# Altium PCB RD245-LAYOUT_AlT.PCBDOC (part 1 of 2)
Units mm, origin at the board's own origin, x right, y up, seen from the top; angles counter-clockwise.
Board outline 75 x 91 mm, 4 copper layers (TOP, Mid-Layer 1, Mid-Layer 2, BOTTOM), stack 0.711 mm thick; 95 components, 67 nets, 327 pads, 801 vias.
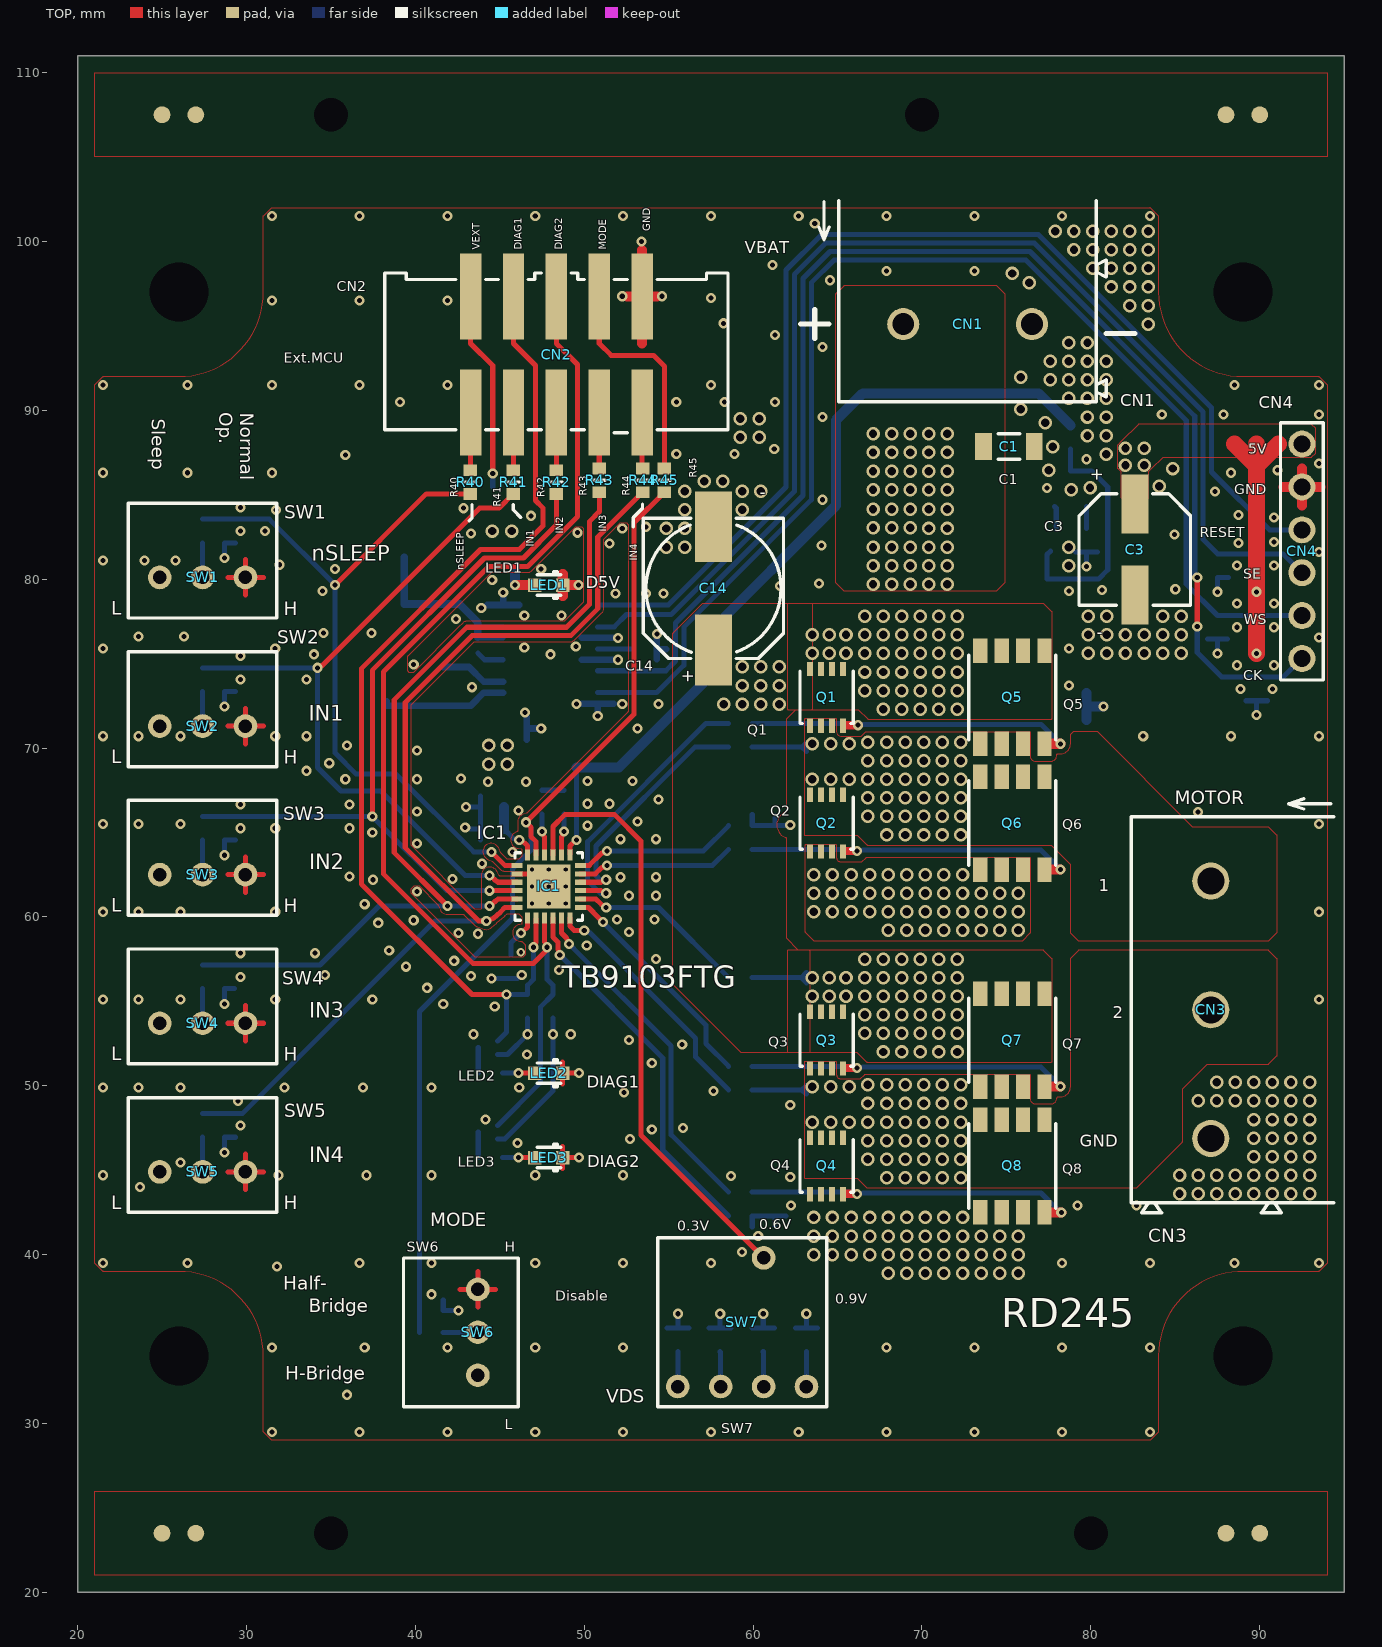
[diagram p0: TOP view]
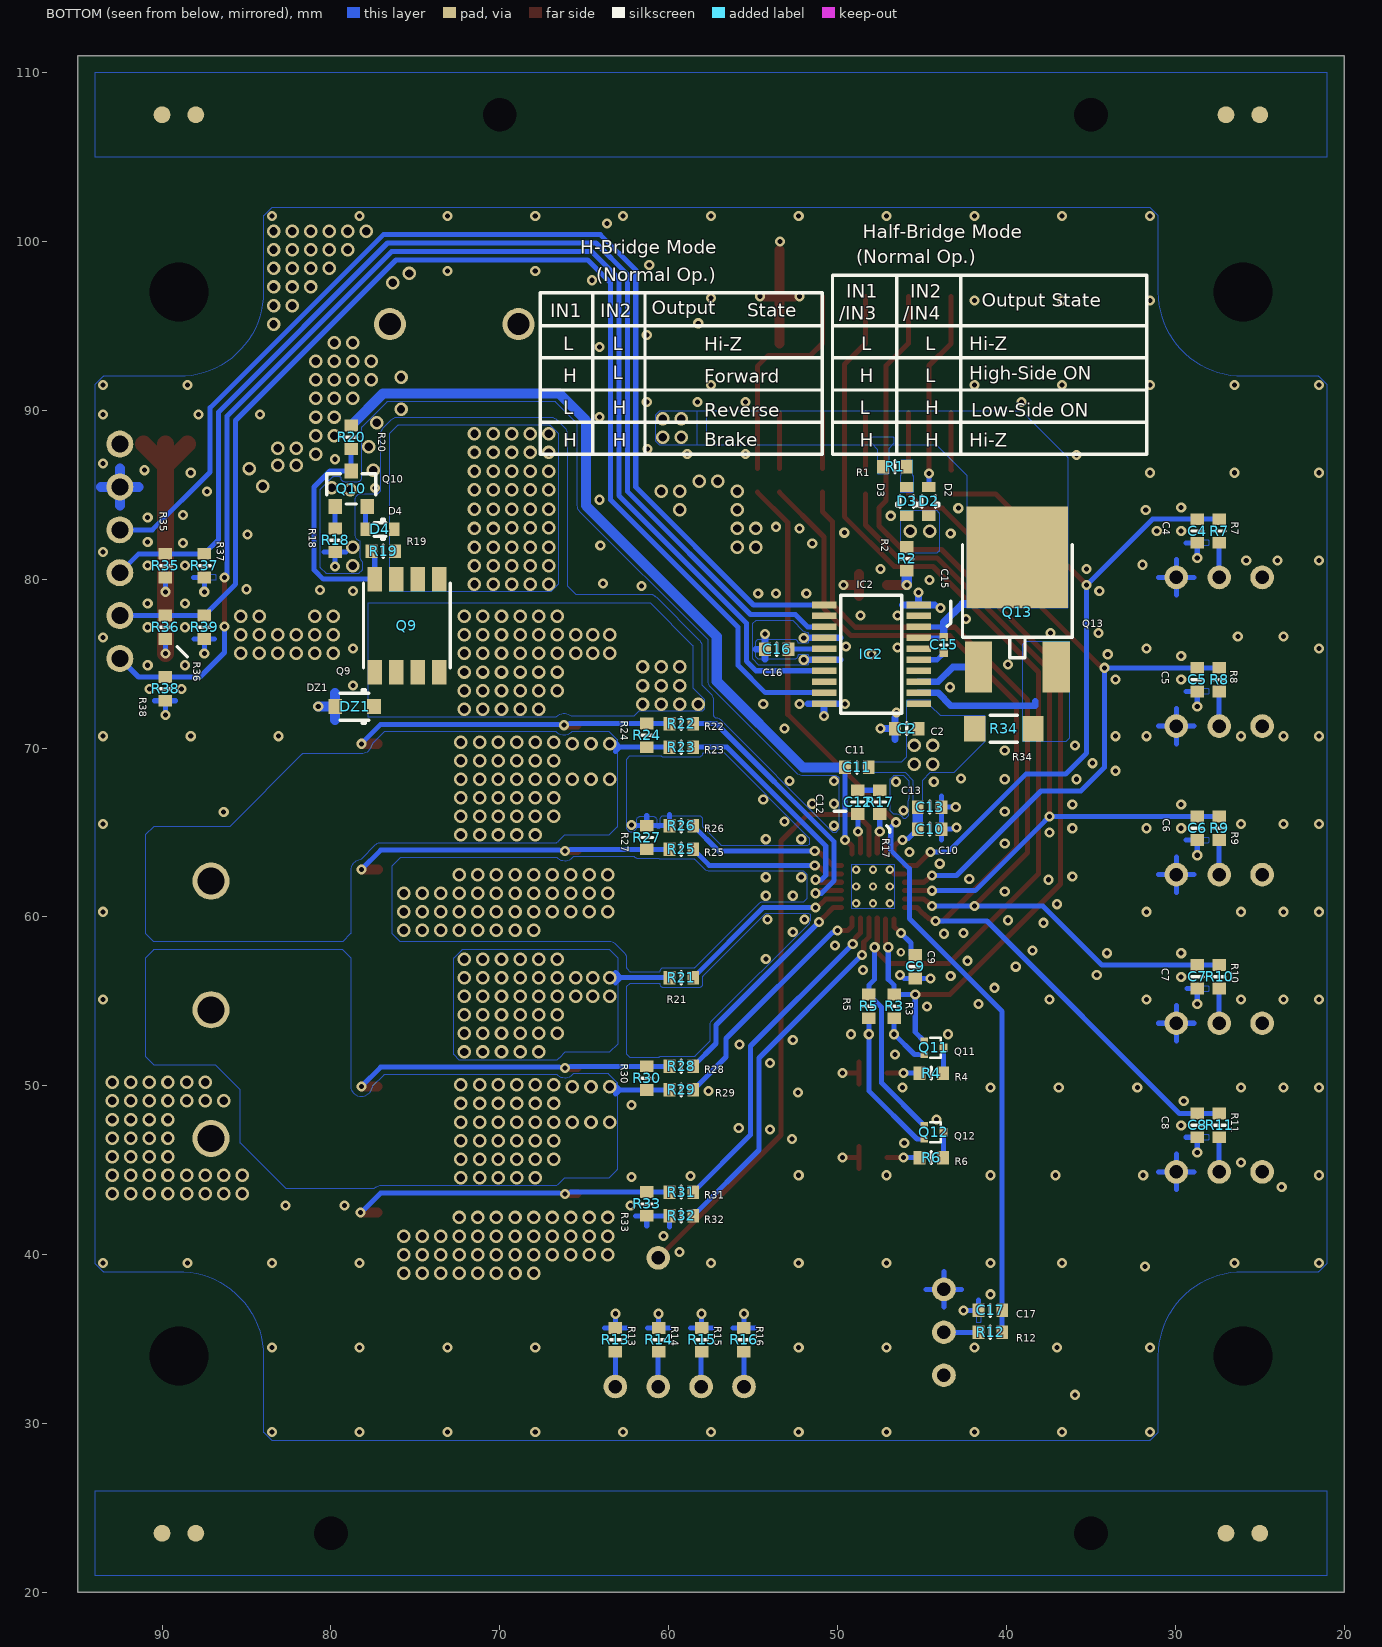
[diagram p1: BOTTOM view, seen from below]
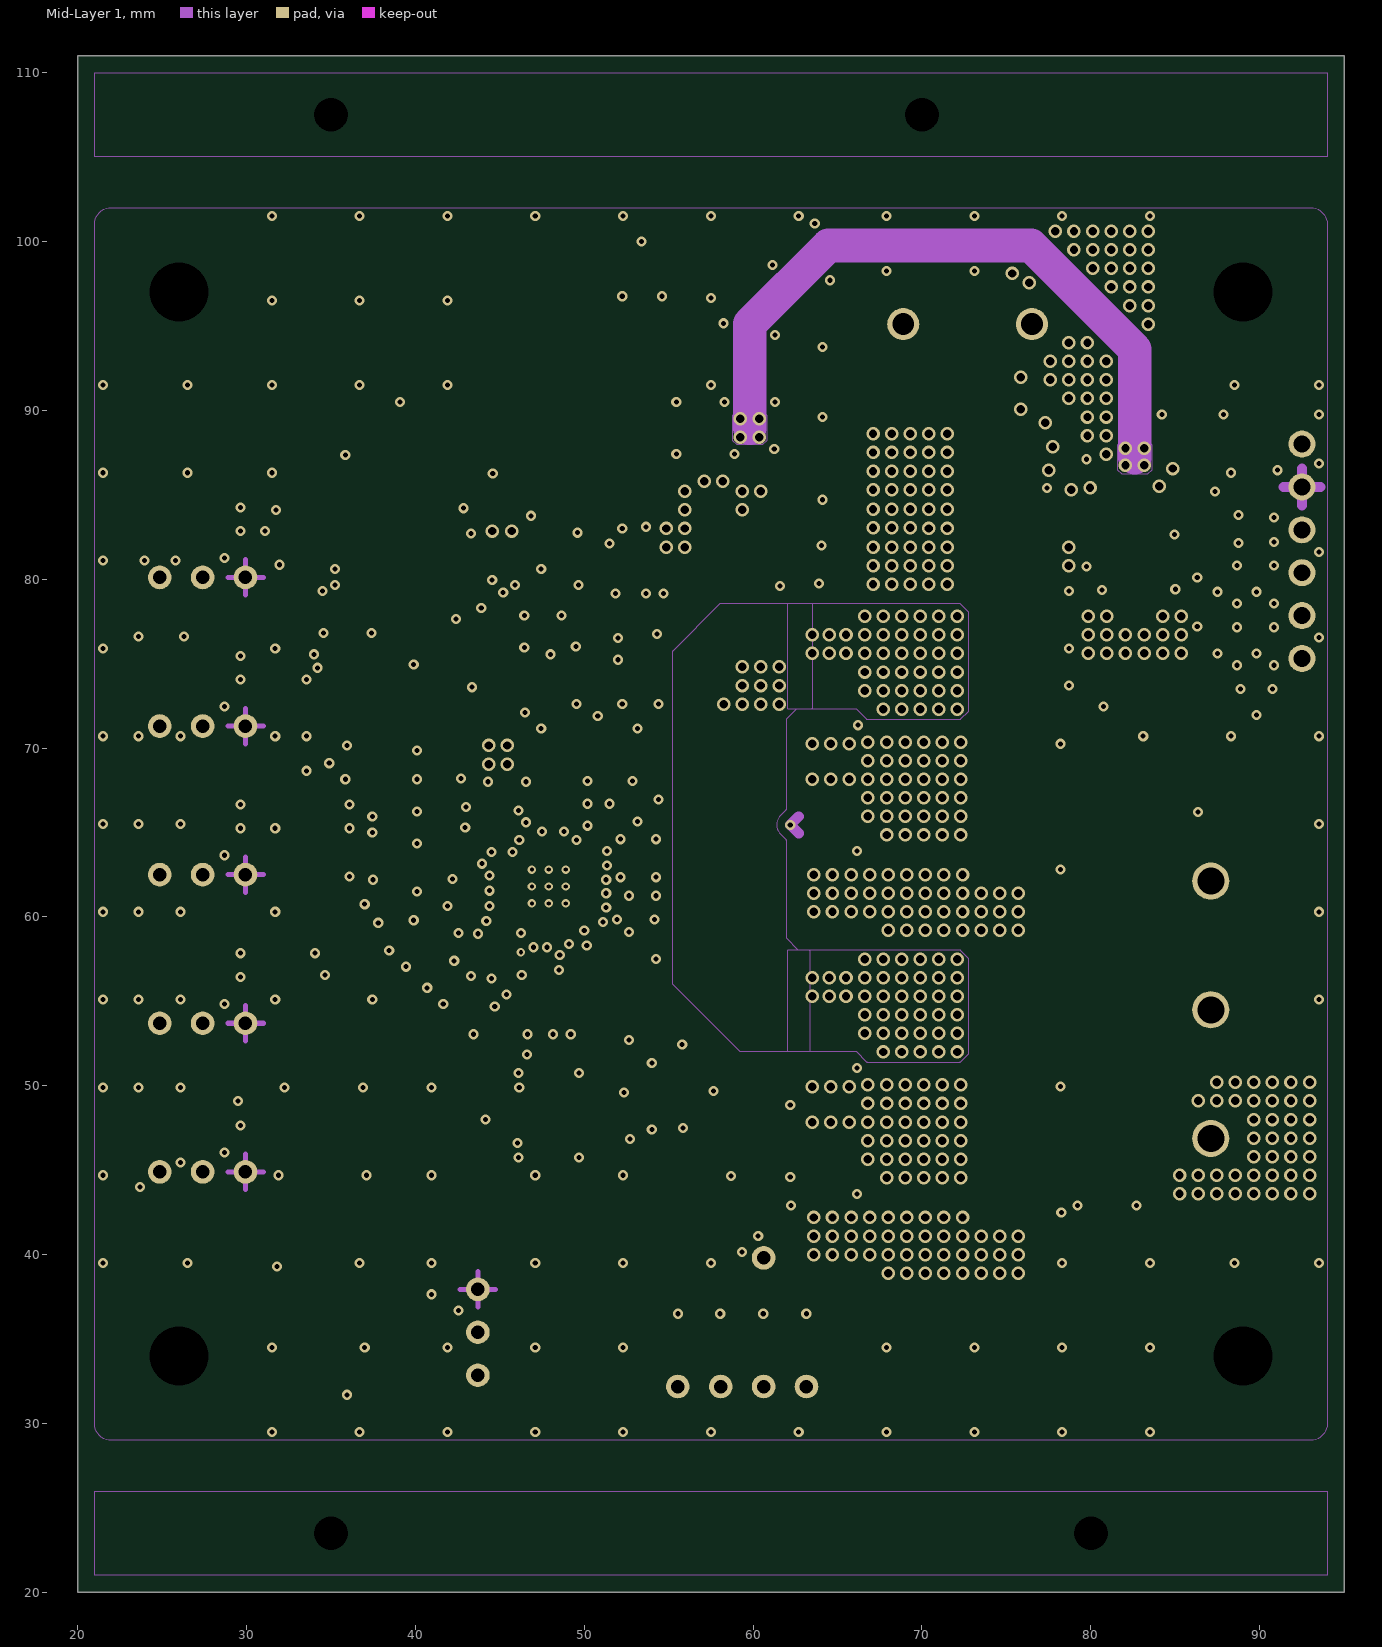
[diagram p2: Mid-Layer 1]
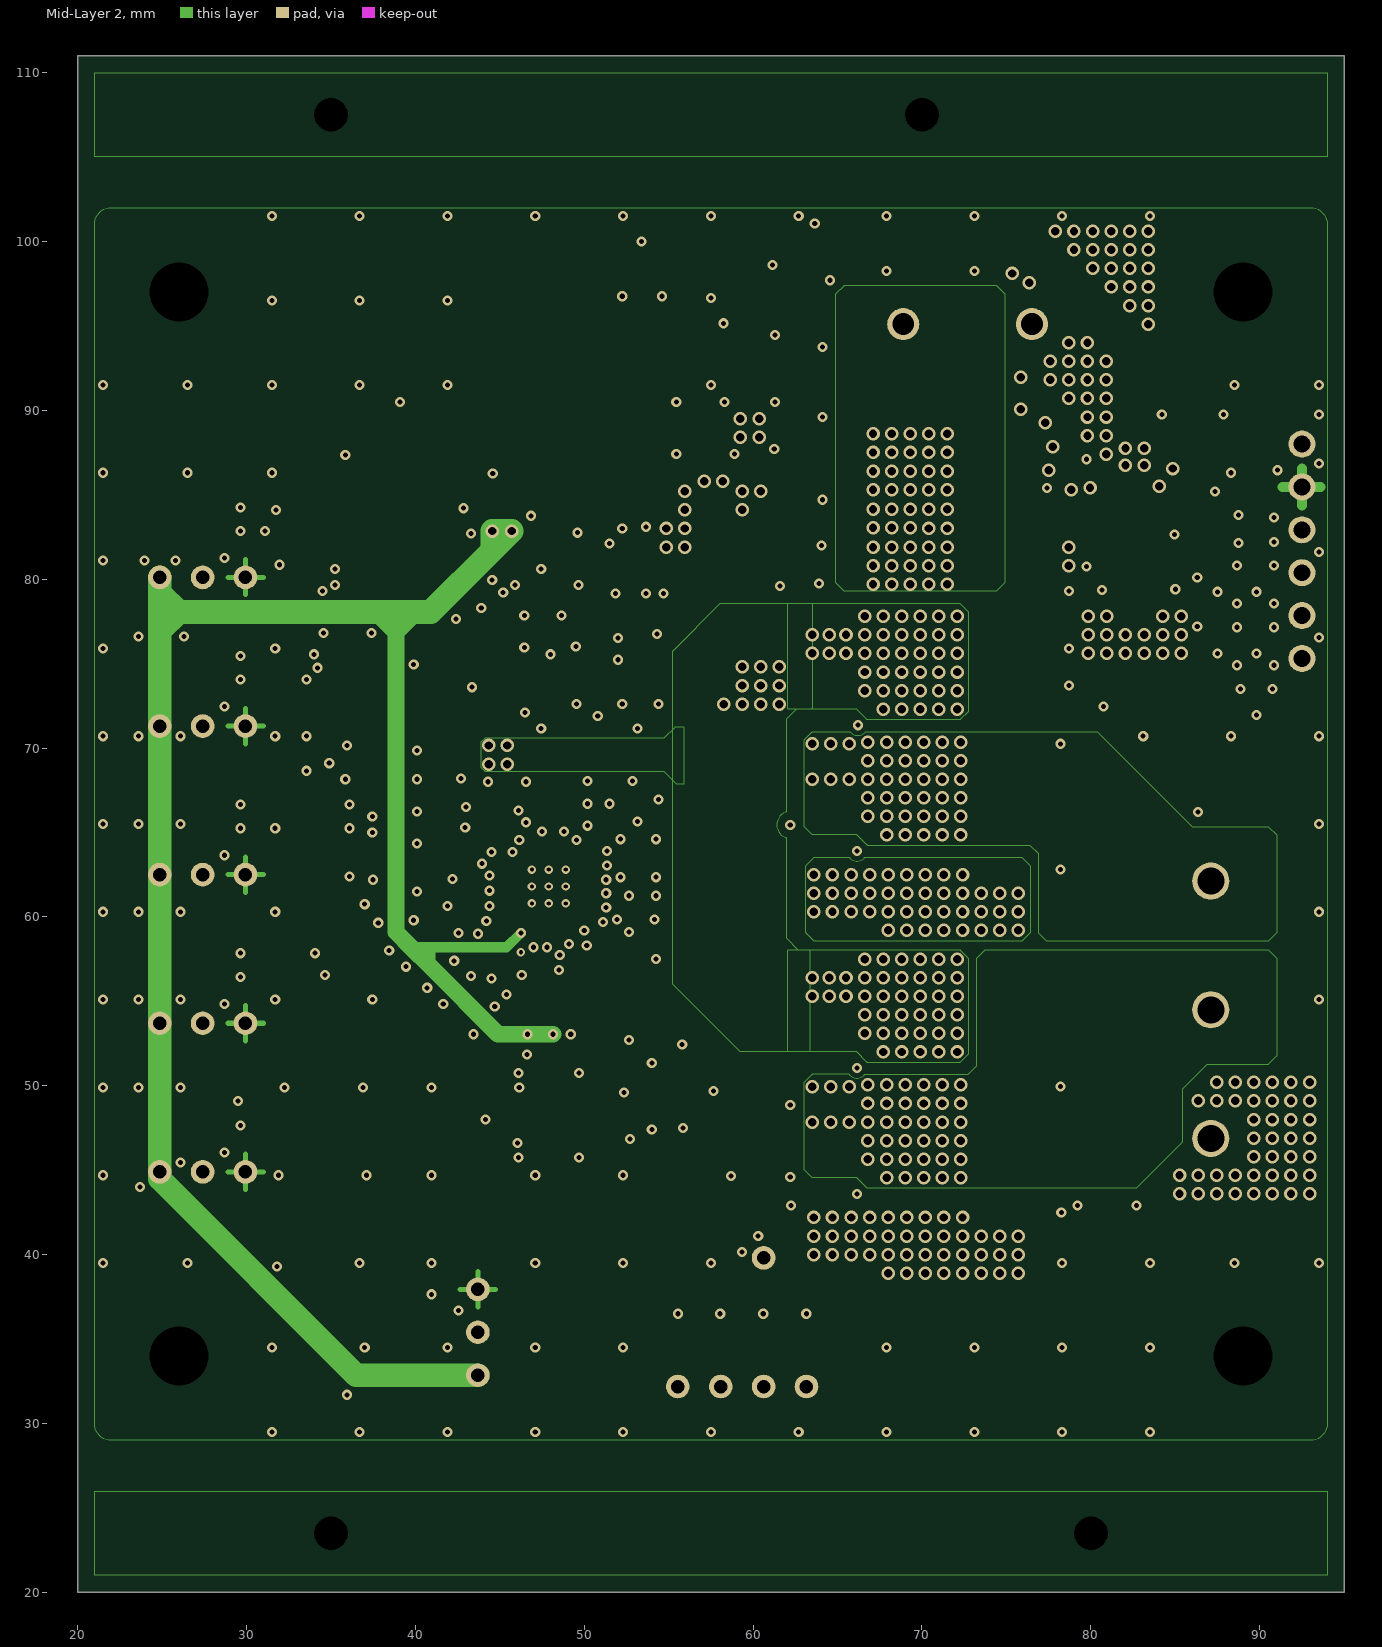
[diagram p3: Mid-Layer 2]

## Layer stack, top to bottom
Top Solder: solder mask 0.0102, Solder Resist, Dk 3.5
TOP: signal copper (thickness not stored)
Mid-Layer 1: signal copper 0.0356
Dielectric2: dielectric 0.32, FR-4, Dk 4.8
Mid-Layer 2: signal copper 0.0356
Dielectric3: dielectric 0.32, FR-4, Dk 4.8
BOTTOM: signal copper (thickness not stored)
Bottom Solder: solder mask 0.0102, Solder Resist, Dk 3.5

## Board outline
20,20 20,111 95,111 95,20

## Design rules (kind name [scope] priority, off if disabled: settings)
AssemblyTestPointUsage [All] p0: scope1count=1 scope1_0_kind=Board scope1_0_value=Board scope2count=1 scope2_0_kind=Board scope2_0_value=Board commentlength=0
AssemblyTestpoint [All] p0: scope1count=1 scope1_0_kind=Board scope1_0_value=Board scope2count=1 scope2_0_kind=Board scope2_0_value=Board commentlength=0
Clearance [All] p0: scope1count=1 scope1_0_kind=Board scope1_0_value=Board scope2count=1 scope2_0_kind=Board scope2_0_value=Board commentlength=0 gap=0.2
Clearance [All] p1: gap=0.2 ignorepadtopadclearanceinfootprint=TRUE except(0.15: SMDPad-Fill SMDPad-Poly SMDPad-Region; 1: Arc-Hole Track-Hole SMDPad-Hole THPad-Hole Via-Hole Fill-Hole Poly-Hole Region-Hole Text-Hole)
ComponentClearance [All] p0: scope1count=1 scope1_0_kind=Board scope1_0_value=Board scope2count=1 scope2_0_kind=Board scope2_0_value=Board commentlength=0 gap=0.254 collisioncheckmode=3
DiffPairsRouting [All] p0: scope1count=1 scope1_0_kind=Board scope1_0_value=Board scope2count=1 scope2_0_kind=Board scope2_0_value=Board commentlength=0
FabricationTestPointUsage [All] p0: scope1count=1 scope1_0_kind=Board scope1_0_value=Board scope2count=1 scope2_0_kind=Board scope2_0_value=Board commentlength=0 valid=0 allowmultiple=FALSE
FabricationTestpoint [All] p0: scope1count=1 scope1_0_kind=Board scope1_0_value=Board scope2count=1 scope2_0_kind=Board scope2_0_value=Board commentlength=0 side=3 testpointundercomponent=TRUE minsize=1.016 maxsize=2.54 preferedsize=1.524 minholesize=0 maxholesize=1.016 preferedholesize=0.813 testpointgrid=0.025
FanoutControl Fanout_Default [All] p0: scope1count=1 scope1_0_kind=Board scope1_0_value=Board scope2count=1 scope2_0_kind=Board scope2_0_value=Board commentlength=30 // Fanout_Default (Default Rule)
FanoutControl Fanout_Small [All] p0 off: scope1count=1 scope1_0_kind=Board scope1_0_value=Board scope2count=1 scope2_0_kind=Board scope2_0_value=Board commentlength=84 // Protel DXP Scope 1 Expression Was: (CompPinCount < 5)   Fanout_Small (Default Rule)
FanoutControl Fanout_SOIC [All] p0 off: scope1count=1 scope1_0_kind=Board scope1_0_value=Board scope2count=1 scope2_0_kind=Board scope2_0_value=Board commentlength=71 // Protel DXP Scope 1 Expression Was: IsSOIC   Fanout_SOIC (Default Rule)
FanoutControl Fanout_LCC [All] p0 off: scope1count=1 scope1_0_kind=Board scope1_0_value=Board scope2count=1 scope2_0_kind=Board scope2_0_value=Board commentlength=69 // Protel DXP Scope 1 Expression Was: IsLCC   Fanout_LCC (Default Rule)
FanoutControl Fanout_BGA [All] p0 off: scope1count=1 scope1_0_kind=Board scope1_0_value=Board scope2count=1 scope2_0_kind=Board scope2_0_value=Board commentlength=69 // Protel DXP Scope 1 Expression Was: IsBGA   Fanout_BGA (Default Rule)
Height [All] p0: scope1count=1 scope1_0_kind=Board scope1_0_value=Board scope2count=1 scope2_0_kind=Board scope2_0_value=Board commentlength=0
HoleSize [All] p0: scope1count=1 scope1_0_kind=Board scope1_0_value=Board scope2count=1 scope2_0_kind=Board scope2_0_value=Board commentlength=0 absolutevalues=TRUE maxlimit=100 minlimit=0.001 maxpercent=80.000 minpercent=20.000
HoleSize [All] p1: absolutevalues=TRUE maxlimit=100 minlimit=0.001 maxpercent=80.000 minpercent=20.000
HoleToHoleClearance [All] p0: scope1count=1 scope1_0_kind=Board scope1_0_value=Board scope2count=1 scope2_0_kind=Board scope2_0_value=Board commentlength=0
HoleToHoleClearance [All] p1: gap=0.5 allowstackedmicrovias=FALSE
LayerPairs [All] p0: scope1count=1 scope1_0_kind=Board scope1_0_value=Board scope2count=1 scope2_0_kind=Board scope2_0_value=Board commentlength=0 enforce=TRUE
MinimumSolderMaskSliver [All] p0: scope1count=1 scope1_0_kind=Board scope1_0_value=Board scope2count=1 scope2_0_kind=Board scope2_0_value=Board commentlength=0
MinimumSolderMaskSliver [All] p1: minsoldermaskwidth=0.1
NetAntennae [All] p0: scope1count=1 scope1_0_kind=Board scope1_0_value=Board scope2count=1 scope2_0_kind=Board scope2_0_value=Board commentlength=0
NetAntennae [All] p1: netantennaetolerance=100
PasteMaskExpansion [All] p0: scope1count=1 scope1_0_kind=Board scope1_0_value=Board scope2count=1 scope2_0_kind=Board scope2_0_value=Board commentlength=0 expansion=0
PlaneClearance [All] p0: scope1count=1 scope1_0_kind=Board scope1_0_value=Board scope2count=1 scope2_0_kind=Board scope2_0_value=Board commentlength=0 clearance=0.001
PlaneClearance [All] p1: clearance=0.001
PlaneConnect [All] p0: scope1count=1 scope1_0_kind=Board scope1_0_value=Board scope2count=1 scope2_0_kind=Board scope2_0_value=Board commentlength=0 planeconnectstyle=Direct reliefexpansion=0.508 reliefentries=4 reliefconductorwidth=0.254 reliefairgap=0.254
PlaneConnect [All] p1: planeconnectstyle=Direct reliefexpansion=0.508 reliefentries=4 reliefconductorwidth=0.254 reliefairgap=0.254
PolygonConnect [All] p0: scope1count=1 scope1_0_kind=Board scope1_0_value=Board scope2count=1 scope2_0_kind=Board scope2_0_value=Board commentlength=0 connectstyle=Direct reliefconductorwidth=0.254 reliefentries=4 polygonreliefangle="90 Angle"
PolygonConnect [All] p1: connectstyle=Direct reliefconductorwidth=0.254 reliefentries=4 polygonreliefangle="90 Angle" airgapwidth=0.254
RoutingCorners [All] p0: scope1count=1 scope1_0_kind=Board scope1_0_value=Board scope2count=1 scope2_0_kind=Board scope2_0_value=Board commentlength=0 cornerstyle=45-Degree minsetback=2.54 maxsetback=2.54
RoutingLayers [All] p0: scope1count=1 scope1_0_kind=Board scope1_0_value=Board scope2count=1 scope2_0_kind=Board scope2_0_value=Board commentlength=0 top layer=Automatic mid layer 1=Automatic mid layer 2=Automatic bottom layer=Automatic
RoutingPriority [All] p0: scope1count=1 scope1_0_kind=Board scope1_0_value=Board scope2count=1 scope2_0_kind=Board scope2_0_value=Board commentlength=0
RoutingTopology [All] p0: scope1count=1 scope1_0_kind=Board scope1_0_value=Board scope2count=1 scope2_0_kind=Board scope2_0_value=Board commentlength=0 topology=Shortest
RoutingVias [All] p0: scope1count=1 scope1_0_kind=Board scope1_0_value=Board scope2count=1 scope2_0_kind=Board scope2_0_value=Board commentlength=0 holewidth=0.1 width=0.1 viastyle="Through Hole" minholewidth=0.001 minwidth=0.001 maxholewidth=100 maxwidth=100
RoutingVias [All] p1: holewidth=0.1 width=0.1 viastyle="Through Hole" minholewidth=0.001 minwidth=0.001 maxholewidth=100 maxwidth=100
ShortCircuit [All] p0: scope1count=1 scope1_0_kind=Board scope1_0_value=Board scope2count=1 scope2_0_kind=Board scope2_0_value=Board commentlength=0 allowed=FALSE
SilkToBoardRegionClearance [All] p0: scope1count=1 scope1_0_kind=Board scope1_0_value=Board scope2count=1 scope2_0_kind=Board scope2_0_value=Board commentlength=0
SilkToSilkClearance [All] p0: scope1count=1 scope1_0_kind=Board scope1_0_value=Board scope2count=1 scope2_0_kind=Board scope2_0_value=Board commentlength=0
SilkToSilkClearance [All] p1: silktosilkclearance=0.001
SilkToSolderMaskClearance [All] p0 off: scope1count=1 scope1_0_kind=Board scope1_0_value=Board scope2count=1 scope2_0_kind=Board scope2_0_value=Board commentlength=44 // Protel DXP Scope 1 Expression Was: IsPad
SilkToSolderMaskClearance [IsPad] p1: minsilkscreentomaskgap=0.05 clearancetoexposedcopper=TRUE
SolderMaskExpansion [All] p0: scope1count=1 scope1_0_kind=Board scope1_0_value=Board scope2count=1 scope2_0_kind=Board scope2_0_value=Board commentlength=0 expansion=0.001
SolderMaskExpansion [All] p1: expansion=0.001
UnRoutedNet [All] p0: scope1count=1 scope1_0_kind=Board scope1_0_value=Board scope2count=1 scope2_0_kind=Board scope2_0_value=Board commentlength=0
UnpouredPolygon [All] p0: scope1count=1 scope1_0_kind=Board scope1_0_value=Board scope2count=1 scope2_0_kind=Board scope2_0_value=Board commentlength=0
Width [All] p0: scope1count=1 scope1_0_kind=Board scope1_0_value=Board scope2count=1 scope2_0_kind=Board scope2_0_value=Board commentlength=0 maxlimit=1000 minlimit=2539.975 preferedwidth=0
Width [All] p1: maxlimit=1000 minlimit=2539.975 preferedwidth=0 toplayer_minwidth=0 midlayer1_minwidth=0 midlayer2_minwidth=0 bottomlayer_minwidth=0 minimp=50.000000 maximp=50.000000 favimp=50.000000
22 further rules are at their usual default settings.

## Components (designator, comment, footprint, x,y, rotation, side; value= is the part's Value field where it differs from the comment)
C1 "Chip3216_GS_3" Chip3216_GS_3 75.15,87.85 r0 top
C2 "Chip1608_GS_1" Chip1608_GS_1#1 45.9,71.15 r0 bottom
C3 "AC_S_6.3x5.8L_NPC" AC_S_6.3x5.8L_NPC 82.6,81.75 r180 top
C4 "Chip1608_GS_1" Chip1608_GS_1#1 28.7,82.85 r270 bottom
C5 "Chip1608_GS_1" Chip1608_GS_1#1 28.7,74.05 r270 bottom
C6 "Chip1608_GS_1" Chip1608_GS_1#1 28.7,65.25 r270 bottom
C7 "Chip1608_GS_1" Chip1608_GS_1#1 28.7,56.45 r270 bottom
C8 "Chip1608_GS_1" Chip1608_GS_1#1 28.7,47.65 r270 bottom
C9 "Chip1608_GS_1" Chip1608_GS_1#1 45.4,57.05 r270 bottom
C10 "Chip1608_GS_1" Chip1608_GS_1#1 44.55,65.2 r180 bottom
C11 "Chip1608_GS_1" Chip1608_GS_1#1 48.85,68.85 r0 bottom
C12 "Chip1608_GS_1" Chip1608_GS_1#1 48.8,66.8 r90 bottom
C13 "Chip1608_GS_1" Chip1608_GS_1#1 44.55,66.5 r180 bottom
C14 "AC_S_8x10L_NPC_B" AC_S_8x10L_NPC_B 57.65,79.45 r0 top
C15 "Chip1005_GS_2" Chip1005_GS_2 43.7,76.1 r90 bottom
C16 "Chip1608_GS_1" Chip1608_GS_1#1 53.6,75.85 r180 bottom
C17 "Chip1608_GS_1" Chip1608_GS_1#1 40.95,36.7 r0 bottom
CN1 "TM_I_1868076_PC_A" TM_I_1868076_PC_A 72.7,95.1 r180 top
CN2 "HP_S_HTST-105-01-L-DV_SC" HP_S_HTST-105-01-L-DV_SC 48.35,93.3 r0 top
CN3 "TM_I_TB005-762-03_CU" TM_I_TB005-762-03_CU 87.1,54.5 r90 top
CN4 "HP_I_M20-99906**_HW" HP_I_M20-99906**_HW 92.5,81.65 r270 top
D2 "DI_S_SOD523_2_TS_A" DI_S_SOD523_2_TS_A 44.6,84.6 r90 bottom
D3 "DI_S_SOD523_2_TS_A" DI_S_SOD523_2_TS_A 45.9,84.6 r90 bottom
D4 "DI_S_SOD523_2_TS_A" DI_S_SOD523_2_TS_A 77.1,82.95 r0 bottom
DZ1 "DI_S_USC_TS" DI_S_USC_TS 78.6,72.45 r180 bottom
IC1 "IC_S_QFN_24E_0.5_GS_5" IC_S_QFN_24E_0.5_GS_5 47.9,61.8 r0 top
IC2 "IC_S_SOP_20_0.65_TS_1" IC_S_SOP_20_0.65_TS_1 48,75.55 r270 bottom
LED1 "LD_S_SML-D12_RM_B" LD_S_SML-D12_RM_B 47.9,79.65 r180 top
LED2 "LD_S_SML-D12_RM_B" LD_S_SML-D12_RM_B 47.9,50.75 r180 top
LED3 "LD_S_SML-D12_RM_B" LD_S_SML-D12_RM_B 47.9,45.75 r180 top
Q1 "TR_S_SON-ADVANCE_TS_2" TR_S_SON-ADVANCE_TS_2 64.35,73 r0 top
Q2 "TR_S_SON-ADVANCE_TS_2" TR_S_SON-ADVANCE_TS_2 64.35,65.55 r0 top
Q3 "TR_S_SON-ADVANCE_TS_2" TR_S_SON-ADVANCE_TS_2 64.35,52.7 r0 top
Q4 "TR_S_SON-ADVANCE_TS_2" TR_S_SON-ADVANCE_TS_2 64.35,45.25 r0 top
Q5 "TR_S_SOP-ADVANCE_TS" TR_S_SOP-ADVANCE_TS#1 75.35,73 r0 top
Q6 "TR_S_SOP-ADVANCE_TS" TR_S_SOP-ADVANCE_TS#1 75.35,65.55 r0 top
Q7 "TR_S_SOP-ADVANCE_TS" TR_S_SOP-ADVANCE_TS#1 75.35,52.7 r0 top
Q8 "TR_S_SOP-ADVANCE_TS" TR_S_SOP-ADVANCE_TS#1 75.35,45.25 r0 top
Q9 "TR_S_SOP-ADVANCE_TS" TR_S_SOP-ADVANCE_TS#2 75.5,77.25 r180 bottom
Q10 "TR_S_SOT23F_3_0.95_TS_B" TR_S_SOT23F_3_0.95_TS_B 78.8,85.35 r0 bottom
Q11 "TR_S_SOT723_3_0.4_TS_A" TR_S_SOT723_3_0.4_TS_A 44.3,52.25 r90 bottom
Q12 "TR_S_SOT723_3_0.4_TS_A" TR_S_SOT723_3_0.4_TS_A 44.3,47.25 r90 bottom
Q13 "TR_S_2-7J1S_TS" TR_S_2-7J1S_TS 39.35,79.3 r0 bottom
R1 "Chip1608_GS_1" Chip1608_GS_1#1 46.6,86.65 r0 bottom
R2 "Chip1608_GS_1" Chip1608_GS_1#1 45.9,81.2 r90 bottom
R3 "Chip1608_GS_1" Chip1608_GS_1#1 46.65,54.7 r270 bottom
R4 "Chip1608_GS_1" Chip1608_GS_1#1 44.45,50.75 r180 bottom
R5 "Chip1608_GS_1" Chip1608_GS_1#1 48.15,54.7 r270 bottom
R6 "Chip1608_GS_1" Chip1608_GS_1#1 44.45,45.75 r180 bottom
R7 "Chip1608_GS_1" Chip1608_GS_1#1 27.4,82.85 r270 bottom
R8 "Chip1608_GS_1" Chip1608_GS_1#1 27.4,74.05 r270 bottom
R9 "Chip1608_GS_1" Chip1608_GS_1#1 27.4,65.25 r270 bottom
R10 "Chip1608_GS_1" Chip1608_GS_1#1 27.4,56.45 r270 bottom
R11 "Chip1608_GS_1" Chip1608_GS_1#1 27.4,47.65 r270 bottom
R12 "Chip1608_GS_1" Chip1608_GS_1#1 40.95,35.4 r0 bottom
R13 "Chip1608_GS_1" Chip1608_GS_1#1 63.15,34.95 r270 bottom
R14 "Chip1608_GS_1" Chip1608_GS_1#1 60.6,34.95 r270 bottom
R15 "Chip1608_GS_1" Chip1608_GS_1#1 58.05,34.95 r270 bottom
R16 "Chip1608_GS_1" Chip1608_GS_1#1 55.55,34.95 r270 bottom
R17 "Chip1608_GS_1" Chip1608_GS_1#1 47.5,66.8 r90 bottom
R18 "Chip1608_GS_1" Chip1608_GS_1#1 79.75,82.3 r90 bottom
R19 "Chip1608_GS_1" Chip1608_GS_1#1 76.9,81.65 r180 bottom
R20 "Chip1608_GS_1" Chip1608_GS_1#1 78.8,88.4 r270 bottom
R21 "Chip1608_GS_1" Chip1608_GS_1#1 59.25,56.4 r0 bottom
R22 "Chip1608_GS_1" Chip1608_GS_1#1 59.25,71.45 r0 bottom
R23 "Chip1608_GS_1" Chip1608_GS_1#1 59.25,70.05 r0 bottom
R24 "Chip1608_GS_1" Chip1608_GS_1#1 61.3,70.75 r90 bottom
R25 "Chip1608_GS_1" Chip1608_GS_1#1 59.25,64 r0 bottom
R26 "Chip1608_GS_1" Chip1608_GS_1#1 59.25,65.4 r0 bottom
R27 "Chip1608_GS_1" Chip1608_GS_1#1 61.3,64.7 r270 bottom
R28 "Chip1608_GS_1" Chip1608_GS_1#1 59.25,51.15 r0 bottom
R29 "Chip1608_GS_1" Chip1608_GS_1#1 59.25,49.75 r0 bottom
R30 "Chip1608_GS_1" Chip1608_GS_1#1 61.3,50.45 r90 bottom
R31 "Chip1608_GS_1" Chip1608_GS_1#1 59.25,43.7 r0 bottom
R32 "Chip1608_GS_1" Chip1608_GS_1#1 59.25,42.3 r0 bottom
R33 "Chip1608_GS_1" Chip1608_GS_1#1 61.3,43 r90 bottom
R34 "R_S_ERJ8B_PN" R_S_ERJ8B_PN 40.15,71.15 r0 bottom
R35 "Chip1608_GS_1" Chip1608_GS_1#1 89.8,80.8 r90 bottom
R36 "Chip1608_GS_1" Chip1608_GS_1#1 89.8,77.15 r90 bottom
R37 "Chip1608_GS_1" Chip1608_GS_1#1 87.5,80.8 r270 bottom
R38 "Chip1608_GS_1" Chip1608_GS_1#1 89.8,73.5 r270 bottom
R39 "Chip1608_GS_1" Chip1608_GS_1#1 87.5,77.15 r270 bottom
R40 "Chip1608_GS_1" Chip1608_GS_1#2 43.25,85.75 r90 top
R41 "Chip1608_GS_1" Chip1608_GS_1#2 45.8,85.75 r90 top
R42 "Chip1608_GS_1" Chip1608_GS_1#2 48.35,85.75 r90 top
R43 "Chip1608_GS_1" Chip1608_GS_1#2 50.9,85.85 r90 top
R44 "Chip1608_GS_1" Chip1608_GS_1#2 53.45,85.85 r90 top
R45 "Chip1608_GS_1" Chip1608_GS_1#2 54.75,85.85 r270 top
SW1 "SW_I_B-1**P_NK" SW_I_B-1**P_NK 27.4,80.1 r90 top
SW2 "SW_I_B-1**P_NK" SW_I_B-1**P_NK 27.4,71.3 r90 top
SW3 "SW_I_B-1**P_NK" SW_I_B-1**P_NK 27.4,62.5 r90 top
SW4 "SW_I_B-1**P_NK" SW_I_B-1**P_NK 27.4,53.7 r90 top
SW5 "SW_I_B-1**P_NK" SW_I_B-1**P_NK 27.4,44.9 r90 top
SW6 "SW_I_B-1**P_NK" SW_I_B-1**P_NK 43.7,35.4 r180 top
SW7 "SW_I_S-2150_CO_A" SW_I_S-2150_CO_A 59.35,36 r180 top

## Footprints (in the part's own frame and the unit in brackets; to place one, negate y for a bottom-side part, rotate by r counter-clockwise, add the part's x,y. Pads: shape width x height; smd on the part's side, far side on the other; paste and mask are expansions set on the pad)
AC_S_6.3x5.8L_NPC [mm] "KC00080BKP"
  rect 1.6x3.5 smd paste-3.6 mask+0: 1(0,2.7) 2(0,-2.7)
  silkscreen extent -3.3,-3.3 3.3,3.3
AC_S_8x10L_NPC_B [mm] "KC00080BKP"
  rect 2.2x4.2 smd paste-4.3 mask+0: 1(0,3.65) 2(0,-3.65)
  silkscreen extent -4.15,-4.15 4.15,4.15
Chip1005_GS_2 [mm] "KC00080BKP"
  rect 0.45x0.5 smd paste-0.6 mask+0: 1(0.475,0) 2(-0.475,0)
  silkscreen extent 0,-0.2 0,0.2
Chip1608_GS_1#1 [mm] "KC00080BKP"
  rect 0.7x0.8 smd paste-0.9 mask+0: 1(0.7,0) 2(-0.7,0)
  silkscreen extent 0,-0.35 0,0.35
Chip1608_GS_1#2 [mm] "KC00080BKP"
  rect 0.7x0.8 smd paste-0.9 mask+0: 1(-0.7,0) 2(0.7,0)
  silkscreen extent 0,-0.35 0,0.35
Chip3216_GS_3 [mm] "KC00080BKP"
  rect 1x1.6 smd paste-1.7 mask+0: 1(-1.5,0) 2(1.5,0)
  silkscreen extent -0.65,-0.75 0.65,0.75
DI_S_SOD523_2_TS_A [mm] "KC00080BKP"
  rect 0.6x0.8 smd paste-0.9 mask+0: A(0.85,0) K(-0.85,0)
  silkscreen extent -0.35,-0.6 0.35,0.6
DI_S_USC_TS [mm] "KC00080BKP"
  rect 0.8x0.9 smd paste-1 mask+0: A(-1.15,0) C(1.15,0)
  silkscreen extent -0.85,-1 0.85,1
HP_I_M20-99906**_HW [mm] "KC00080BKP"
  round 1.6 hole 1 paste-1.7 mask+0: 1(-6.35,0) 2(-3.81,0) 3(-1.27,0) 4(1.27,0) 5(3.81,0) 6(6.35,0)
  silkscreen extent -7.62,-1.27 7.62,1.27
HP_S_HTST-105-01-L-DV_SC [mil] "KC00080BKP"
  rect 50x200 smd paste-203.94 mask+0: 1(-200,-135) 2(-200,135) 3(-100,-135) 4(-100,135) 5(0,-135) 6(0,135) 7(100,-135) 8(100,135) 9(200,-135) 10(200,135)
  silkscreen extent -400,-182 400,190
IC_S_QFN_24E_0.5_GS_5 [mm] "KC00080BKP"
  rect 0.3x0.65 smd paste-0.75 mask+0: 1(-1.25,-1.875) 2(-0.75,-1.875) 3(-0.25,-1.875) 4(0.25,-1.875) 5(0.75,-1.875) 6(1.25,-1.875) 13(1.25,1.875) 14(0.75,1.875) 15(0.25,1.875) 16(-0.25,1.875) 17(-0.75,1.875) 18(-1.25,1.875)
  rect 0.65x0.3 smd paste-0.75 mask+0: 7(1.875,-1.25) 8(1.875,-0.75) 9(1.875,-0.25) 10(1.875,0.25) 11(1.875,0.75) 12(1.875,1.25) 19(-1.875,1.25) 20(-1.875,0.75) 21(-1.875,0.25) 22(-1.875,-0.25) 23(-1.875,-0.75) 24(-1.875,-1.25)
  rect 2.6x2.6 smd paste-2.7 mask+0: EPAD(0,0)
  silkscreen extent -2,-2 2,2
IC_S_SOP_20_0.65_TS_1 [mm] "KC00080BKP"
  rect 0.4x1.45 smd paste-1.55 mask+0: 1(2.925,2.8) 2(2.275,2.8) 3(1.625,2.8) 4(0.975,2.8) 5(0.325,2.8) 6(-0.325,2.8) 7(-0.975,2.8) 8(-1.625,2.8) 9(-2.275,2.8) 10(-2.925,2.8) 11(-2.925,-2.8) 12(-2.275,-2.8) 13(-1.625,-2.8) 14(-0.975,-2.8) 15(-0.325,-2.8) 16(0.325,-2.8) 17(0.975,-2.8) 18(1.625,-2.8) 19(2.275,-2.8) 20(2.925,-2.8)
  silkscreen extent -3.5,-1.8 3.5,1.8
LD_S_SML-D12_RM_B [mm] "KC00080BKP"
  rect 0.8x0.8 smd paste-0.9 mask+0: A(0.825,0) K(-0.825,0)
  silkscreen extent -0.7,-0.8 0.7,0.8
R_S_ERJ8B_PN [mm] "KC00080BKP"
  rect 1.25x1.5 smd paste-1.6 mask+0: 1(1.725,0) 2(-1.725,0)
  silkscreen extent -0.81,-0.8 0.81,0.8
SW_I_B-1**P_NK [mm] "KC00080BKP"
  round 1.4 hole 0.8 paste-1.5 mask+0: 1(0,2.54) 2(0,0) 3(0,-2.54)
  silkscreen extent -2.4,-4.4 4.4,4.4
SW_I_S-2150_CO_A [mm] "KC00080BKP"
  round 1.4 hole 0.8 paste-1.5 mask+0: 1(-3.81,3.81) 2(-1.27,3.81) 3(1.27,3.81) 4(3.81,3.81) C(-1.27,-3.81)
  silkscreen extent -5,-5 5,5
TM_I_1868076_PC_A [mm] "KC00080BKP"
  round 1.9 hole 1.3 paste-2 mask+0: 1(3.81,0) 2(-3.81,0)
  silkscreen extent -8.2,-7.3 8.8,4.6
TM_I_TB005-762-03_CU [mm] "KC00080BKP"
  round 2.2 hole 1.6 paste-2.3 mask+0: 1(7.62,0) 2(0,0) 3(-7.62,0)
  silkscreen extent -12.03,-7.3 12.49,4.7
TR_S_2-7J1S_TS [mm] "KC00080BKP"
  rect 1.6x3 smd paste-3.1 mask+0: B(2.3,4.5) E(-2.3,4.5)
  rect 6x6 smd paste-6.1 mask+0: C(0,-2)
  silkscreen extent -3.25,-2.75 3.25,3.95
TR_S_SON-ADVANCE_TS_2 [mm] "KC00080BKP"
  rect 0.35x0.85 smd paste-0.95 mask+0: 1(-0.975,-1.675) 2(-0.325,-1.675) 3(0.325,-1.675) 4(0.975,-1.675)
  rect 0.35x0.85 smd paste-0.85 mask+0: 5(0.975,1.675) 6(0.325,1.675) 7(-0.325,1.675) 8(-0.975,1.675)
  silkscreen extent -1.58,-1.55 1.57,1.55
TR_S_SOP-ADVANCE_TS#1 [mm] "KC00080BKP"
  rect 0.85x1.45 smd paste-1.55 mask+0: 1(-1.905,-2.75) 2(-0.635,-2.75) 3(0.635,-2.75) 4(1.905,-2.75) 5(1.905,2.75) 6(0.635,2.75) 7(-0.635,2.75) 8(-1.905,2.75)
  silkscreen extent -2.57,-2.5 2.58,2.5
TR_S_SOP-ADVANCE_TS#2 [mm] "KC00080BKP"
  rect 0.85x1.45 smd paste-1.55 mask+0: 1(1.905,2.75) 2(0.635,2.75) 3(-0.635,2.75) 4(-1.905,2.75) 5(-1.905,-2.75) 6(-0.635,-2.75) 7(0.635,-2.75) 8(1.905,-2.75)
  silkscreen extent -2.58,-2.5 2.57,2.5
TR_S_SOT23F_3_0.95_TS_B [mm] "KC00080BKP"
  rect 0.8x0.9 smd paste-1 mask+0: B(0.95,1.05) C(0,-1.05) E(-0.95,1.05)
  silkscreen extent -1.45,-0.9 1.45,0.9
TR_S_SOT723_3_0.4_TS_A [mm] "KC00080BKP"
  rect 0.5x0.45 smd paste-0.6 mask+0: D(0,-0.575)
  rect 0.4x0.45 smd paste-0.55 mask+0: G(0.4,0.575) S(-0.4,0.575)
  silkscreen extent -0.6,-0.4 0.6,0.2

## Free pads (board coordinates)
  round 1 / inner round 0 / far side round 1 all layers, no hole paste-2 mask+0: ""(25,23.5) ""(25,107.5) ""(90,23.5) ""(90,107.5)
  round 0 hole 3.5 unplated paste-3.9 mask+0: ""(26,34) ""(26,97) ""(89,34) ""(89,97)
  round 1 / inner round 0 / far side round 1 all layers, no hole paste-1 mask+0: ""(27,23.5) ""(27,107.5) ""(88,23.5) ""(88,107.5)
  round 0 hole 2 unplated paste-2.4 mask+0: ""(35,23.5) ""(35,107.5) ""(70,107.5) ""(80,23.5)

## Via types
v1: diameter 0.8, hole 0.5, TOP to BOTTOM, 435 vias
v2: diameter 0.6, hole 0.3, TOP to BOTTOM, 356 vias
v3: diameter 0.5, hole 0.25, TOP to BOTTOM, 10 vias

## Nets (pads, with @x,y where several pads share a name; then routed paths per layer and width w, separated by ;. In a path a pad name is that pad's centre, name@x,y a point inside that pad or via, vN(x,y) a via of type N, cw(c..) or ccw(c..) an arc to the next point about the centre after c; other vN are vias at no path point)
D5V: C9.2 D2.K D3.K IC1.1 Q11.S Q12.S R2.1 R3.1 R5.1 SW1.1 SW2.1 SW3.1 SW4.1 SW5.1 SW6.1 | length 144.3
  TOP w0.2: v2(46.25,59.05) 46.55,59.3
  TOP w0.3: 46.55,59.3 46.65,59.4 IC1.1@46.65,59.875
  Mid-Layer 2 w0.6: 39.75,58.2 40.9,58.2 ; 40.9,57.05 40.9,58.2 ; v2(46.25,59.05) 45.4,58.2 40.9,58.2
  Mid-Layer 2 w1: 37.65,78.05 38.85,76.85 ; 38.85,78.05 38.85,76.85 ; 40.05,78.05 38.85,76.85 ; v2(48.15,53.05) v2(46.65,53.05) 44.9,53.05 40.9,57.05 39.75,58.2 38.85,59.1 38.85,76.85
  Mid-Layer 2 w1.4: SW1.1@24.86,80.1 24.86,79.19 ; SW6.1@43.7,32.86 36.49,32.86 24.86,44.49 SW5.1@24.86,44.9 SW4.1@24.86,53.7 SW3.1@24.86,62.5 SW2.1@24.86,71.3 24.86,76.91 ; 24.86,76.91 26,78.05 ; 24.86,76.91 24.86,78.05 ; 24.86,78.05 24.86,79.19 ; 24.86,78.05 26,78.05 ; 24.86,79.19 26,78.05 ; 26,78.05 37.65,78.05 38.85,78.05 40.05,78.05 40.9,78.05 44.55,81.7 ; 44.55,81.7 v1(45.7,82.85) v1(44.55,82.85) 44.55,81.7
  BOTTOM w0.3: Q12.S@44.875,46.85 45.3,46.85 48.15,49.7 v2(48.15,53.05) R5.1@48.15,54 ; Q11.S@44.875,51.85 45.45,51.85 v2(46.65,53.05) R3.1@46.65,54 ; C9.2@45.65,57.75 45.65,58.45 v2(46.25,59.05)
DIAG1: CN2.4 IC1.2 Q11.G R3.2 | length 61.5
  TOP w0.3: v2(45.4,55.4) 43.35,55.4 36.8,61.95 36.8,74.7 43.85,81.75 46.15,81.75 47.55,83.15 47.55,84.22 47.12,84.65 47.12,92.65 45.81,93.96 CN2.4@45.81,96.729 ; v2(47,58.2) 47.15,58.5 IC1.2@47.15,59.875
  BOTTOM w0.3: Q11.G@44.875,52.65 45.4,53.175 v2(45.4,55.4) R3.2@46.65,55.4 46.65,55.95 47,56.3 v2(47,58.2)
DIAG2: CN2.6 IC1.3 Q12.G R5.2 | length 67
  TOP w0.3: IC1.3@47.65,59.925 47.65,58.5 v2(47.8,58.2) 47.65,57.9 47,57.25 43.4,57.25 38.1,62.55 38.1,74.5 44.35,80.75 46.65,80.75 49.6,83.7 49.6,92.71 48.35,93.96 CN2.6@48.35,96.729
  BOTTOM w0.3: Q12.G@44.875,47.65 47.4,50.175 47.4,54.65 R5.2@48.15,55.4 48.15,55.95 47.8,56.3 v2(47.8,58.2)
GH1: IC1.9 R22.2 | length 16.5
  TOP w0.3: IC1.9@49.775,61.55 51,61.55 v2(51.3,61.4)
  BOTTOM w0.3: v2(51.3,61.4) 50.95,61.4 50.2,62.15 50.2,64.45 57.2,71.45 R22.2@58.55,71.45
GH2: IC1.7 R28.2 | length 13.3
  TOP w0.3: IC1.7@49.775,60.55 50.25,60.55 50.85,59.95 v2(51.1,59.7)
  BOTTOM w0.3: v2(51.1,59.7) 57.2,53.6 57.2,52.5 R28.2@58.55,51.15
GL1: IC1.11 R25.2 | length 9.3
  TOP w0.3: IC1.11@49.775,62.55 50.65,62.55 51,62.9 v2(51.35,63.05)
  BOTTOM w0.3: v2(51.35,63.05) 57.6,63.05 R25.2@58.55,64
GL2: IC1.5 R31.2 | length 20.3
  TOP w0.3: IC1.5@48.65,59.925 48.65,59.05 48.95,58.75 v2(49.1,58.4)
  BOTTOM w0.3: v2(49.1,58.4) 49.35,58.15 55.15,52.35 55.15,47.1 R31.2@58.55,43.7
GND: C1.2 C2.1 C3.1 C4.1 C5.1 C6.1 C7.1 C8.1 C9.1 C10.1 C13.1 C14.1 C16.2 C17.1 CN1.2 CN2.10 CN3.3 CN4.2 DZ1.A IC1.20 IC1.EPAD IC2.10 IC2.14 IC2.16 IC2.20 LED1.K LED2.K LED3.K Q2.1 Q2.2 Q2.3 Q4.1 Q4.2 Q4.3 Q6.1 Q6.2 Q6.3 Q8.1 Q8.2 Q8.3 R13.2 R14.2 R15.2 R16.2 R18.2 R26.1 R27.2 R32.1 R33.2 R37.1 R38.1 R39.1 SW1.3 SW2.3 SW3.3 SW4.3 SW5.3 SW6.3 | length 186.5
  TOP w0.3: 28.9,44.9 SW5.3@29.94,44.9 ; 28.9,53.7 SW4.3@29.94,53.7 ; 28.9,62.5 SW3.3@29.94,62.5 ; 28.9,71.3 SW2.3@29.94,71.3 ; 28.9,80.1 SW1.3@29.94,80.1 ; 29.94,43.85 SW5.3@29.94,44.9 ; 29.94,45.95 SW5.3@29.94,44.9 ; 29.94,52.65 SW4.3@29.94,53.7 ; 29.94,54.75 SW4.3@29.94,53.7 ; 29.94,61.45 SW3.3@29.94,62.5 ; 29.94,63.55 SW3.3@29.94,62.5 ; 29.94,70.25 SW2.3@29.94,71.3 ; 29.94,72.35 SW2.3@29.94,71.3 ; 29.94,79.05 SW1.3@29.94,80.1 ; 29.94,81.15 SW1.3@29.94,80.1 ; 31,44.9 SW5.3@29.94,44.9 ; 31,53.7 SW4.3@29.94,53.7 ; 31,62.5 SW3.3@29.94,62.5 ; 31,71.3 SW2.3@29.94,71.3 ; 31,80.1 SW1.3@29.94,80.1 ; 42.65,37.94 SW6.3@43.7,37.94 ; 43.7,36.9 SW6.3@43.7,37.94 ; 43.7,39 SW6.3@43.7,37.94 ; 44.75,37.94 SW6.3@43.7,37.94 ; IC1.20@46.025,62.55 IC1.EPAD@46.65,62.55 ; 48.725,45.1 LED3.K@48.725,45.75 48.725,46.4 ; 48.725,50.1 LED2.K@48.725,50.75 ; 48.725,51.4 LED2.K@48.725,50.75 ; LED3.K@48.775,45.75 v2(49.7,45.75) ; v2(49.7,50.75) LED2.K@48.725,50.75
  TOP w0.6: 48.725,79 LED1.K@48.725,79.65 ; 48.725,80.3 LED1.K@48.725,79.65 ; v2(49.65,79.65) LED1.K@48.725,79.65 ; 52.55,96.729 CN2.10@53.43,96.729 ; 53.43,93.95 CN2.10@53.43,96.729 ; 53.43,99.5 CN2.10@53.43,96.729 ; 54.3,96.729 CN2.10@53.43,96.729 ; 91.4,85.46 CN4.2@92.5,85.46 ; 92.5,84.36 CN4.2@92.5,85.46 ; 92.5,86.56 CN4.2@92.5,85.46 ; 93.6,85.46 CN4.2@92.5,85.46
  Mid-Layer 1 w0.3: 28.9,44.9 SW5.3@29.94,44.9 ; 28.9,53.7 SW4.3@29.94,53.7 ; 28.9,62.5 SW3.3@29.94,62.5 ; 28.9,71.3 SW2.3@29.94,71.3 ; 28.9,80.1 SW1.3@29.94,80.1 ; 29.94,43.85 SW5.3@29.94,44.9 ; 29.94,45.95 SW5.3@29.94,44.9 ; 29.94,52.65 SW4.3@29.94,53.7 ; 29.94,54.75 SW4.3@29.94,53.7 ; 29.94,61.45 SW3.3@29.94,62.5 ; 29.94,63.55 SW3.3@29.94,62.5 ; 29.94,70.25 SW2.3@29.94,71.3 ; 29.94,72.35 SW2.3@29.94,71.3 ; 29.94,79.05 SW1.3@29.94,80.1 ; 29.94,81.15 SW1.3@29.94,80.1 ; 31,44.9 SW5.3@29.94,44.9 ; 31,53.7 SW4.3@29.94,53.7 ; 31,62.5 SW3.3@29.94,62.5 ; 31,71.3 SW2.3@29.94,71.3 ; 31,80.1 SW1.3@29.94,80.1 ; 42.65,37.94 SW6.3@43.7,37.94 ; 43.7,36.9 SW6.3@43.7,37.94 ; 43.7,39 SW6.3@43.7,37.94 ; 44.75,37.94 SW6.3@43.7,37.94
  Mid-Layer 1 w0.6: 62.7,64.95 v2(62.2,65.45) 62.7,65.95 ; 91.4,85.46 CN4.2@92.5,85.46 ; 92.5,84.36 CN4.2@92.5,85.46 ; 92.5,86.56 CN4.2@92.5,85.46 ; 93.6,85.46 CN4.2@92.5,85.46
  Mid-Layer 2 w0.3: 28.9,44.9 SW5.3@29.94,44.9 ; 28.9,53.7 SW4.3@29.94,53.7 ; 28.9,62.5 SW3.3@29.94,62.5 ; 28.9,71.3 SW2.3@29.94,71.3 ; 28.9,80.1 SW1.3@29.94,80.1 ; 29.94,43.85 SW5.3@29.94,44.9 ; 29.94,45.95 SW5.3@29.94,44.9 ; 29.94,52.65 SW4.3@29.94,53.7 ; 29.94,54.75 SW4.3@29.94,53.7 ; 29.94,61.45 SW3.3@29.94,62.5 ; 29.94,63.55 SW3.3@29.94,62.5 ; 29.94,70.25 SW2.3@29.94,71.3 ; 29.94,72.35 SW2.3@29.94,71.3 ; 29.94,79.1 SW1.3@29.94,80.1 ; 29.94,81.15 SW1.3@29.94,80.1 ; 31,44.9 SW5.3@29.94,44.9 ; 31,53.7 SW4.3@29.94,53.7 ; 31,62.5 SW3.3@29.94,62.5 ; 31,71.3 SW2.3@29.94,71.3 ; 31,80.1 SW1.3@29.94,80.1 ; 42.65,37.94 SW6.3@43.7,37.94 ; 43.7,36.9 SW6.3@43.7,37.94 ; 43.7,39 SW6.3@43.7,37.94 ; 44.75,37.94 SW6.3@43.7,37.94
  Mid-Layer 2 w0.6: 91.35,85.46 CN4.2@92.5,85.46 ; 92.5,84.35 CN4.2@92.5,85.46 ; 92.5,86.56 CN4.2@92.5,85.46 ; 93.6,85.46 CN4.2@92.5,85.46
  BOTTOM w0.3: 28.7,46.35 C8.1@28.7,46.95 29.35,46.95 ; v2@28.7,55.15 C7.1@28.7,55.75 29.3,55.75 ; 28.7,63.95 C6.1@28.7,64.55 29.35,64.55 ; 28.7,72.75 C5.1@28.7,73.35 29.35,73.35 ; v2@28.7,81.55 C4.1@28.7,82.15 29.35,82.15 ; 28.9,44.9 SW5.3@29.94,44.9 ; 28.9,53.7 SW4.3@29.94,53.7 ; 28.9,62.5 SW3.3@29.94,62.5 ; 28.9,71.3 SW2.3@29.94,71.3 ; 28.9,80.1 SW1.3@29.94,80.1 ; 29.94,43.85 SW5.3@29.94,44.9 ; 29.94,45.95 SW5.3@29.94,44.9 ; 29.94,52.65 SW4.3@29.94,53.7 ; 29.94,54.75 SW4.3@29.94,53.7 ; 29.94,61.45 SW3.3@29.94,62.5 ; 29.94,63.55 SW3.3@29.94,62.5 ; 29.94,70.25 SW2.3@29.94,71.3 ; 29.94,72.35 SW2.3@29.94,71.3 ; 29.94,79.05 SW1.3@29.94,80.1 ; 29.94,81.15 SW1.3@29.94,80.1 ; 31,44.9 SW5.3@29.94,44.9 ; 31,53.7 SW4.3@29.94,53.7 ; 31,62.5 SW3.3@29.94,62.5 ; 31,71.3 SW2.3@29.94,71.3 ; 31,80.1 SW1.3@29.94,80.1 ; 41.65,37.3 C17.1@41.65,36.7 v2(42.55,36.7) ; 42.65,37.94 SW6.3@43.7,37.94 ; v2(43,66.5) C13.1@43.85,66.5 ; 43.25,65.2 C10.1@43.85,65.2 ; 43.7,36.9 SW6.3@43.7,37.94 ; 43.7,39 SW6.3@43.7,37.94 ; 43.85,64.55 C10.1@43.85,65.2 ; 43.85,67.15 C13.1@43.85,66.5 ; v2(44.5,56.35) C9.1@45.4,56.35 46.05,56.35 ; 44.75,37.94 SW6.3@43.7,37.94 ; 54.9,35.65 R16.2@55.55,35.65 ; v2@55.55,36.25 R16.2@55.55,35.65 ; 56.2,35.65 R16.2@55.55,35.65 ; 57.4,35.65 R15.2@58.05,35.65 ; v2@58.05,36.25 R15.2@58.05,35.65 ; 58.7,35.65 R15.2@58.05,35.65 ; 59.95,35.65 R14.2@60.6,35.65 ; 59.95,41.65 R32.1@59.95,42.3 R33.2@61.3,42.3 ; 59.95,66.05 R26.1@59.95,65.4 R27.2@61.3,65.4 ; v2@60.6,36.25 R14.2@60.6,35.65 ; 61.25,35.65 R14.2@60.6,35.65 ; 61.3,41.7 R33.2@61.3,42.3 ; 61.3,66 R27.2@61.3,65.4 ; 61.95,42.3 R33.2@61.3,42.3 ; v2@62.25,65.4 R27.2@61.3,65.4 ; 62.5,35.65 R13.2@63.15,35.65 ; v2@63.15,36.25 R13.2@63.15,35.65 ; v1@63.6,42.3 v1@63.7,42.2 ; 63.8,35.65 R13.2@63.15,35.65 ; 79.1,81.6 R18.2@79.75,81.6 ; v2(79.75,80.75) R18.2@79.75,81.6 ; 80.4,81.6 R18.2@79.75,81.6 ; 86.9,76.45 R39.1@87.5,76.45 ; v2(87.5,75.6) R39.1@87.5,76.45 ; v2(87.5,79.25) R37.1@87.5,80.1 88.15,80.1 ; 88.1,76.45 R39.1@87.5,76.45 ; 89.2,72.8 R38.1@89.8,72.8 ; v2(89.8,71.95) R38.1@89.8,72.8 ; 90.45,72.8 R38.1@89.8,72.8 ; C10.1@43.85,65.2 C13.1@43.85,66.5
  BOTTOM w0.4: 44.25,78.475 IC2.10@45.2,78.475 ; v2(45.2,79.2) IC2.10@45.2,78.475 ; 46.15,78.475 IC2.10@45.2,78.475 ; 46.6,70.5 C2.1@46.6,71.15 ; 46.6,71.8 C2.1@46.6,71.15 ; v2(47.45,71.15) C2.1@46.6,71.15 ; 49.85,72.625 IC2.20@50.8,72.625 ; 49.85,75.225 IC2.16@50.8,75.225 v2(52,75.225) ; 49.85,76.525 IC2.14@50.8,76.525 v2(52,76.525) ; v2(50.8,71.9) IC2.20@50.8,72.625 ; 51.75,72.625 IC2.20@50.8,72.625 ; 54.3,75.25 C16.2@54.3,75.85 ; v2(54.3,76.75) C16.2@54.3,75.85 ; 54.85,75.85 C16.2@54.3,75.85
  BOTTOM w0.6: 79.75,71.65 DZ1.A@79.75,72.45 ; 79.75,73.25 DZ1.A@79.75,72.45 ; v2(80.75,72.45) DZ1.A@79.75,72.45 ; 91.4,85.46 CN4.2@92.5,85.46 ; 92.5,84.36 CN4.2@92.5,85.46 ; 92.5,86.56 CN4.2@92.5,85.46 ; 93.6,85.46 CN4.2@92.5,85.46
  other v1: 68,38.9 69.1,38.9 70.2,38.9 71.3,38.9 72.4,38.9 73.5,38.9 74.6,38.9 75.7,38.9 63.6,40 64.7,40 65.8,40 66.9,40 68,40 69.1,40 70.2,40 71.3,40 72.4,40 73.5,40 74.6,40 75.7,40 63.6,41.1 64.7,41.1 65.8,41.1 66.9,41.1 68,41.1 69.1,41.1 70.2,41.1 71.3,41.1 72.4,41.1 73.5,41.1 74.6,41.1 75.7,41.1 63.6,42.2 64.7,42.2 65.8,42.2 66.9,42.2 68,42.2 69.1,42.2 70.2,42.2 71.3,42.2 72.4,42.2 85.25,43.6 86.35,43.6 87.45,43.6 88.55,43.6 89.65,43.6 90.75,43.6 91.85,43.6 92.95,43.6 85.25,44.7 86.35,44.7 87.45,44.7 88.55,44.7 89.65,44.7 90.75,44.7 91.85,44.7 92.95,44.7 89.65,45.8 90.75,45.8 91.85,45.8 92.95,45.8 89.65,46.9 90.75,46.9 91.85,46.9 92.95,46.9 89.65,48 90.75,48 91.85,48 92.95,48 86.35,49.1 87.45,49.1 88.55,49.1 89.65,49.1 90.75,49.1 91.85,49.1 92.95,49.1 87.45,50.2 88.55,50.2 89.65,50.2 90.75,50.2 91.85,50.2 92.95,50.2 68,59.2 69.1,59.2 70.2,59.2 71.3,59.2 72.4,59.2 73.5,59.2 74.6,59.2 75.7,59.2 63.6,60.3 64.7,60.3 65.8,60.3 66.9,60.3 68,60.3 69.1,60.3 70.2,60.3 71.3,60.3 72.4,60.3 73.5,60.3 74.6,60.3 75.7,60.3 63.6,61.4 64.7,61.4 65.8,61.4 66.9,61.4 68,61.4 69.1,61.4 70.2,61.4 71.3,61.4 72.4,61.4 73.5,61.4 74.6,61.4 75.7,61.4 63.6,62.5 64.7,62.5 65.8,62.5 66.9,62.5 68,62.5 69.1,62.5 70.2,62.5 71.3,62.5 72.4,62.5 79.85,75.6 80.95,75.6 82.05,75.6 83.15,75.6 84.25,75.6 85.35,75.6 79.85,76.7 80.95,76.7 82.05,76.7 83.15,76.7 84.25,76.7 85.35,76.7 79.85,77.8 80.95,77.8 84.25,77.8 85.35,77.8 78.7,80.8 54.85,81.9 55.95,81.9 78.7,81.9 54.85,83 55.95,83 55.95,84.1 59.35,84.1 55.95,85.2 59.35,85.2 60.45,85.2 78.85,85.3 79.95,85.4 84.05,85.5 57.1,85.8 58.2,85.8 77.5,86.45 84.85,86.55 80.9,87.4 77.75,87.85 79.8,88.5 80.9,88.5 77.3,89.25 79.8,89.6 80.9,89.6 75.85,90.05 78.7,90.7 79.8,90.7 80.9,90.7 77.6,91.8 78.7,91.8 79.8,91.8 80.9,91.8 75.85,91.95 77.6,92.9 78.7,92.9 79.8,92.9 80.9,92.9 78.7,94 79.8,94 83.4,95.1 82.3,96.2 83.4,96.2 81.2,97.3 82.3,97.3 83.4,97.3 76.35,97.55 75.35,98.1 80.1,98.4 81.2,98.4 82.3,98.4 83.4,98.4 79,99.5 80.1,99.5 81.2,99.5 82.3,99.5 83.4,99.5 77.9,100.6 79,100.6 80.1,100.6 81.2,100.6 82.3,100.6 83.4,100.6
  other v2: 31.5,29.5 36.7,29.5 41.9,29.5 47.1,29.5 52.3,29.5 57.5,29.5 62.7,29.5 67.9,29.5 73.1,29.5 78.3,29.5 83.5,29.5 35.95,31.7 31.5,34.5 37,34.5 41.9,34.5 47.1,34.5 52.3,34.5 67.9,34.5 73.1,34.5 78.3,34.5 83.5,34.5 55.55,36.5 58.05,36.5 60.6,36.5 63.15,36.5 40.95,37.65 31.8,39.3 21.5,39.5 26.5,39.5 36.7,39.5 40.95,39.5 47.1,39.5 52.3,39.5 57.5,39.5 78.3,39.5 83.5,39.5 88.5,39.5 93.5,39.5 59.35,40.15 60.3,41.1 62.25,42.9 79.2,42.9 82.7,42.9 23.7,44 62.2,44.6 58.7,44.65 21.5,44.7 31.9,44.7 37.1,44.7 40.95,44.7 47.1,44.7 52.3,44.7 26.1,45.45 28.7,46.05 46.05,46.6 52.7,46.85 54,47.4 55.85,47.5 29.65,47.65 44.15,48 62.2,48.85 29.5,49.1 52.35,49.6 57.65,49.7 21.5,49.9 23.6,49.9 26.1,49.9 32.25,49.9 36.9,49.9 40.95,49.9 46.15,49.9 54,51.35 46.6,51.85 55.8,52.45 52.65,52.7 43.45,53.05 49.2,53.05 44.7,54.7 28.7,54.85 41.65,54.85 21.5,55.1 23.6,55.1 26.1,55.1 31.7,55.1 37.45,55.1 93.5,55.1 40.7,55.8 29.65,56.45 43.3,56.5 34.65,56.55 46.3,56.55 48.5,56.85 39.45,57.05 42.3,57.4 54.25,57.5 29.65,57.85 34.05,57.85 38.45,58 50.15,58.3 43.7,59 42.55,59.05 52.65,59.1 37.8,59.65 39.9,59.8 51.95,59.85 54.15,59.85 21.5,60.3 23.6,60.3 26.1,60.3 31.7,60.3 93.5,60.3 37,60.75 52.65,61.25 54.25,61.25 40.1,61.5 37.5,62.2 42.2,62.25 52.15,62.35 54.25,62.35 36.1,62.4 43.95,63.15 28.7,63.65 45.75,63.85 40.1,64.35 52.15,64.6 54.25,64.6 37.45,65 29.65,65.25 31.7,65.25 36.1,65.25 42.95,65.3 50.2,65.4 21.5,65.5 23.6,65.5 26.1,65.5 93.5,65.5 53.15,65.65 86.35,66.2 40.1,66.25 46.1,66.3 29.65,66.65 36.1,66.65 50.2,66.7 51.5,66.7 54.4,66.95 44.3,68 46.55,68 50.2,68.05 52.85,68.05 35.85,68.15 40.1,68.15 42.7,68.2 33.55,68.65 34.9,69.1 40.1,69.85 35.95,70.15 21.5,70.7 23.6,70.7 26.1,70.7 31.7,70.7 33.55,70.7 83.1,70.7 88.3,70.7 93.5,70.7 53.15,71.15 46.5,72.1 28.7,72.45 49.55,72.6 52.25,72.6 54.4,72.6 88.85,73.5 90.75,73.5 43.35,73.6 78.7,73.7 29.65,74.05 33.55,74.05 88.65,74.9 90.85,74.9 39.9,74.95 29.65,75.45 34,75.55 48,75.55 21.5,75.9 31.7,75.9 78.7,75.9 46.45,75.95 49.5,76 93.5,76.55 23.6,76.6 26.3,76.6 34.55,76.8 37.4,76.8 88.65,77.15 90.85,77.15 42.4,77.65 46.45,77.85 48.65,77.85 43.9,78.3 88.65,78.55 90.85,78.55 51.85,79.15 53.65,79.15 54.7,79.15 34.5,79.3 78.7,79.3 80.65,79.35 85,79.4 61.6,79.6 63.9,79.75 44.55,79.95 35.25,80.6 47.45,80.6 88.65,80.8 90.85,80.8 31.95,80.85 21.5,81.1 23.95,81.1 25.8,81.1 28.7,81.25 93.5,81.6 64.05,82 51.5,82.1 88.75,82.15 90.85,82.2 84.95,82.65 43.3,82.7 49.6,82.75 29.65,82.85 31.1,82.85 52.25,83 53.65,83.1 90.85,83.65 46.85,83.75 88.75,83.8 31.75,84.1 42.85,84.2 29.65,84.25 64.1,84.7 87.35,85.2 77.4,85.4 21.5,86.3 26.5,86.3 31.5,86.3 88.3,86.3 91.05,86.45 93.5,86.85 79.75,87.1 35.85,87.35 55.45,87.4 58.9,87.4 61.25,87.7 64.1,89.6 84.2,89.75 87.85,89.75 93.5,89.75 39.1,90.5 55.45,90.5 58.3,90.5 61.3,90.5 21.5,91.5 26.5,91.5 31.5,91.5 36.7,91.5 41.9,91.5 57.5,91.5 88.5,91.5 93.5,91.5 64.1,93.75 61.3,94.45 58.25,95.15 31.5,96.5 36.7,96.5 41.9,96.5 57.5,96.65 52.25,96.75 54.6,96.75 64.55,97.7 67.9,98.25 73.1,98.25 61.15,98.6 53.4,100 63.65,101.05 31.5,101.5 36.7,101.5 41.9,101.5 47.1,101.5 52.3,101.5 57.5,101.5 62.7,101.5 67.9,101.5 73.1,101.5 78.3,101.5 83.5,101.5
  other v3: 46.25,57.9 46.9,60.8 47.9,60.8 48.9,60.8 46.9,61.8 47.9,61.8 48.9,61.8 46.9,62.8 47.9,62.8 48.9,62.8
IN1: C5.2 IC1.21 R8.2 R41.1 | length 43.2
  TOP w0.3: v2(34.2,74.75) 34.5,74.9 43.8,84.2 44.95,84.2 R41.1@45.8,85.05 ; v2(44.4,62.45) 44.7,62.2 44.9,62.05 IC1.21@46.025,62.05
  BOTTOM w0.3: R8.2@27.4,74.75 C5.2@28.7,74.75 v2(34.2,74.75) 34.2,68.85 35.6,67.45 37.95,67.45 42.95,62.45 v2(44.4,62.45)
IN2: C6.2 IC1.22 R9.2 R42.1 | length 45.4
  TOP w0.3: v2(37.45,65.95) 37.45,74.6 44.1,81.25 46.4,81.25 48.35,83.2 R42.1@48.35,85.05 ; v2(44.4,61.55) IC1.22@46.025,61.55
  BOTTOM w0.3: R9.2@27.4,65.95 C6.2@28.7,65.95 v2(37.45,65.95) 37.7,65.7 41.85,61.55 v2(44.4,61.55)
IN3: C7.2 IC1.23 R10.2 R43.1 | length 54.5
  TOP w0.3: v2(41.9,60.65) 38.75,63.8 38.75,72.85 43.05,77.15 48.95,77.15 50.3,78.5 50.3,83.4 50.9,84 R43.1@50.9,85.15 ; v2(44.4,60.65) 44.7,60.9 44.9,61.05 IC1.23@46.025,61.05
  BOTTOM w0.3: R10.2@27.4,57.15 C7.2@28.7,57.15 34.35,57.15 37.85,60.65 v2(41.9,60.65) v2(44.4,60.65)
IN4: C8.2 IC1.24 R11.2 R44.1 | length 60.5
  TOP w0.3: IC1.24@46.025,60.55 45.3,60.55 45.05,60.3 44.6,59.9 v2(44.2,59.75) 43.75,59.75 39.4,64.1 39.4,72.7 43.35,76.65 49.2,76.65 50.8,78.25 50.8,82.5 R44.1@53.45,85.15
  BOTTOM w0.3: R11.2@27.4,48.35 C8.2@28.7,48.35 29.75,48.35 41.15,59.75 v2(44.2,59.75)
MODE: C17.2 IC1.17 R12.2 R45.2 | length 58.2
  TOP w0.3: IC1.17@47.15,63.675 47.15,64.45 46.85,64.75 46.85,65.3 46.8,65.35 v2(46.55,65.6) 52.95,72 52.95,83.35 R45.2@54.75,85.15
  BOTTOM w0.3: R12.2@40.25,35.4 C17.2@40.25,36.7 40.25,54.4 45.75,59.9 45.75,62.85 46.85,63.95 46.85,65.3 v2(46.55,65.6)
N453078: LED1.A R2.2 | length 2
  TOP w0.6: v2(45.9,79.65) LED1.A@47.075,79.65
  BOTTOM w0.6: v2(45.9,79.65) R2.2@45.9,80.5
N469486: R16.1 SW7.4 | length 2.1
  BOTTOM w0.3: SW7.4@55.54,32.19 55.54,34.24 R16.1@55.55,34.25
N469495: R15.1 SW7.3 | length 2.1
  BOTTOM w0.3: R15.1@58.05,34.25 58.08,34.22 SW7.3@58.08,32.19
N469504: R14.1 SW7.2 | length 2.1
  BOTTOM w0.3: R14.1@60.6,34.25 60.62,34.23 SW7.2@60.62,32.19
N469513: R13.1 SW7.1 | length 2.1
  BOTTOM w0.3: R13.1@63.15,34.25 63.16,34.24 SW7.1@63.16,32.19
N470308: Q12.D R6.1 | length 1.5
  BOTTOM w0.3: Q12.D@43.725,47.25 43.725,45.775 R6.1@43.75,45.75
N470324: LED3.A R6.2 | length 1.9
  TOP w0.3: v2(46.1,45.75) LED3.A@47.075,45.75
  BOTTOM w0.3: R6.2@45.15,45.75 v2(46.1,45.75)
N471565: Q11.D R4.1 | length 1.5
  BOTTOM w0.3: Q11.D@43.725,52.25 43.725,50.775 R4.1@43.75,50.75
N472312: LED2.A R4.2 | length 1.9
  TOP w0.3: v2(46.1,50.75) LED2.A@47.075,50.75
  BOTTOM w0.3: R4.2@45.15,50.75 v2(46.1,50.75)
N500947: Q9.4 Q10.C R19.2 R20.1 | length 14.3
  BOTTOM w0.3: R19.2@77.6,81.65 77.405,81.455 Q9.4@77.405,80 80.45,80 81,80.55 81,85.45 80.05,86.4 Q10.C@78.8,86.4 R20.1@78.8,87.7
N500987: C11.1 IC1.13 R20.2 | length 49
  TOP w0.2: 49.25,64.3 v2(49.55,64.55)
  TOP w0.3: IC1.13@49.15,63.725 49.15,64.2 49.25,64.3
  BOTTOM w0.3: v2(49.55,64.55) C11.1@49.55,68.85
  BOTTOM w0.6: C11.1@49.55,68.85 52.05,68.85 57.15,73.95 57.15,76.6 64.9,84.35 64.9,89.4 66.5,91 76.9,91 R20.2@78.8,89.1
N501039: C12.2 IC1.14 | length 2.4
  TOP w0.3: IC1.14@48.65,63.775 48.65,64.7 v2(48.8,65.05)
  BOTTOM w0.3: v2(48.8,65.05) C12.2@48.8,66.1
N501211: C12.1 R17.1 | length 1.3
  BOTTOM w0.3: R17.1@47.5,67.5 C12.1@48.8,67.5
N501689: Q1.4 Q5.4 R22.1 R24.1 | length 20.5
  TOP w0.5: Q1.4@65.4,71.35 v2(66.2,71.35)
  TOP w0.6: Q5.4@77.255,70.25 v2(78.2,70.25)
  BOTTOM w0.3: R22.1@59.95,71.45 R24.1@61.3,71.45 65.85,71.45 v2(66.2,71.35) 66.55,71.4 77.05,71.4 v2(78.2,70.25)
N501775: IC1.12 R26.2 | length 9.7
  TOP w0.3: IC1.12@49.775,63.05 50.3,63.05 51,63.75 v2(51.35,63.9)
  BOTTOM w0.3: v2(51.35,63.9) 57.05,63.9 R26.2@58.55,65.4
N502037: IC1.4 R32.2 | length 21.9
  TOP w0.3: IC1.4@48.15,59.925 48.15,58.8 48.45,58.5 48.45,58.1 v2(48.55,57.75)
  BOTTOM w0.3: v2(48.55,57.75) 48.8,57.5 54.65,51.65 54.65,46.2 R32.2@58.55,42.3
N502087: Q2.4 Q6.4 R25.1 R27.1 | length 20.5
  TOP w0.5: Q2.4@65.4,63.9 v2(66.15,63.9)
  TOP w0.6: Q6.4@77.205,62.8 Q6.4@77.255,62.8 v2(78.2,62.8)
  BOTTOM w0.3: R25.1@59.95,64 R27.1@61.3,64 65.8,64 v2(66.15,63.9) 66.5,63.95 77.05,63.95 v2(78.2,62.8)
N533770: Q4.4 Q8.4 R31.1 R33.1 | length 20.5
  TOP w0.5: Q4.4@65.4,43.6 v2(66.15,43.6)
  TOP w0.6: Q8.4@77.255,42.5 v2(78.25,42.5)
  BOTTOM w0.3: R31.1@59.95,43.7 R33.1@61.3,43.7 65.8,43.7 v2(66.15,43.6) 66.5,43.65 77.05,43.65 77.95,42.75 v2(78.25,42.5)
N554303: Q3.4 Q7.4 R28.1 R30.1 | length 20.4
  TOP w0.5: Q3.4@65.4,51.05 v2(66.15,51.05)
  TOP w0.6: Q7.4@77.255,49.95 v2(78.2,49.95)
  BOTTOM w0.3: R28.1@59.95,51.15 R30.1@61.3,51.15 65.8,51.15 v2(66.15,51.05) 66.5,51.1 77.05,51.1 v2(78.2,49.95)
N561074: R12.1 SW6.2 | length 2
  BOTTOM w0.3: R12.1@41.65,35.4 SW6.2@43.7,35.4
N573754: R7.1 SW1.2 | length 2.1
  BOTTOM w0.3: SW1.2@27.4,80.1 R7.1@27.4,82.15
N575579: IC1.16 R17.2 | length 2.4
  TOP w0.3: v2(47.5,65.05) 47.65,64.7 IC1.16@47.65,63.775
  BOTTOM w0.3: v2(47.5,65.05) R17.2@47.5,66.1
N576851: IC1.8 R21.2 | length 10.7
  TOP w0.3: IC1.8@49.775,61.05 50.7,61.05 51,60.75 v2(51.3,60.55)
  BOTTOM w0.3: v2(51.3,60.55) 54.4,60.55 R21.2@58.55,56.4
N593239: R8.1 SW2.2 | length 2.1
  BOTTOM w0.3: SW2.2@27.4,71.3 R8.1@27.4,73.35
N593372: R9.1 SW3.2 | length 2.1
  BOTTOM w0.3: SW3.2@27.4,62.5 R9.1@27.4,64.55
N593506: R10.1 SW4.2 | length 2.1
  BOTTOM w0.3: SW4.2@27.4,53.7 R10.1@27.4,55.75
N593641: R11.1 SW5.2 | length 2.1
  BOTTOM w0.3: SW5.2@27.4,44.9 R11.1@27.4,46.95
N607694: Q10.B R18.1 | length 1.3
  BOTTOM w0.3: R18.1@79.75,83 Q10.B@79.75,84.3
N610543: D4.A Q10.E | length 1.4
  BOTTOM w0.3: Q10.E@77.85,84.3 77.95,84.2 D4.A@77.95,82.95
N622087: C3.2 C15.1 CN4.1 IC2.7 IC2.8 Q13.C R1.1 R35.2 R36.2 | length 69.1
  TOP w1: 88.5,88 89.8,86.7 ; v2(89.8,75.6) v2(89.8,79.25) 89.8,86.7 ; 89.8,88 89.8,86.7 ; 91.1,88 89.8,86.7
  Mid-Layer 1 w2: 59.8,88.95 59.8,95.1 64.45,99.75 76.45,99.75 82.6,93.6 82.6,87.2
  BOTTOM w0.3: C15.1@43.7,76.575 43.75,76.525 IC2.7@45.2,76.525 ; 43.7,77.175 IC2.8@45.2,77.175 ; v2(89.8,75.6) R36.2@89.8,76.45 ; v2(89.8,79.25) R35.2@89.8,80.1
  BOTTOM w0.45: Q13.C@39.35,81.3 39.35,78.525 42.625,78.525 43.7,77.45 43.7,77.175 C15.1@43.7,76.575
  other v1: 82.05,86.75 83.15,86.75 82.05,87.75 83.15,87.75 59.25,88.4 60.35,88.4 59.25,89.5 60.35,89.5
N622351: C16.1 IC2.15 | length 2.1
  BOTTOM w0.3: IC2.15@50.8,75.875 52.875,75.875 C16.1@52.9,75.9
N628803: CN4.3 IC2.11 | length 67.8
  BOTTOM w0.3: IC2.11@50.8,78.475 54.975,78.475 61.95,85.45 61.95,98.3 64.05,100.4 76.9,100.4 87.15,90.15 87.15,86.35 90.58,82.92 CN4.3@92.5,82.92
N642892: CN2.8 R45.1 | length 13.2
  TOP w0.3: CN2.8@50.89,96.729 50.89,93.96 51.6,93.25 54.1,93.25 54.75,92.6 R45.1@54.75,86.55
N665551: D3.A R1.2
N4658670: CN2.1 R40.2 | length 3.4
  TOP w0.3: R40.2@43.25,86.45 43.27,86.47 CN2.1@43.27,89.871
N4658672: CN2.3 R41.2 | length 3.4
  TOP w0.3: R41.2@45.8,86.45 45.81,86.46 CN2.3@45.81,89.871
N4658674: CN2.5 R42.2 | length 3.4
  TOP w0.3: R42.2@48.35,86.45 CN2.5@48.35,89.871
N4658676: CN2.7 R43.2 | length 3.3
  TOP w0.3: CN2.7@50.89,89.871 50.89,86.56 R43.2@50.9,86.55
N4658678: CN2.9 R44.2 | length 3.3
  TOP w0.3: CN2.9@53.43,89.871 53.43,86.57 R44.2@53.45,86.55
N6221411: C15.2 IC2.5 | length 1.7
  BOTTOM w0.3: C15.2@43.7,75.625 44.1,75.225 IC2.5@45.2,75.225
NSLEEP: C4.2 IC1.19 R7.2 R40.1 | length 43.2
  TOP w0.3: v2(35.25,79.65) 40.65,85.05 R40.1@43.25,85.05 ; v2(44.5,63.85) 45.3,63.05 IC1.19@46.025,63.05
  BOTTOM w0.3: R7.2@27.4,83.55 C4.2@28.7,83.55 31.35,83.55 v2(35.25,79.65) 35.25,69.7 36.5,68.45 38.85,68.45 43.45,63.85 v2(44.5,63.85)
OUT1: CN3.1 Q1.1 Q1.2 Q1.3 Q2.5 Q2.6 Q2.7 Q2.8 Q5.1 Q5.2 Q5.3 Q6.5 Q6.6 Q6.7 Q6.8 R23.1 R24.2 | length 4.4
  BOTTOM w0.3: R23.1@59.95,70.05 R24.2@61.3,70.05 62.9,70.05 ; 63.15,69.8 62.9,70.05 ; v1@63.15,70.3 62.9,70.05 ; v1@63.5,70.35 63.2,70.05 62.9,70.05
  other v1: 67.9,64.85 69,64.85 70.1,64.85 71.2,64.85 72.3,64.85 66.8,65.95 67.9,65.95 69,65.95 70.1,65.95 71.2,65.95 72.3,65.95 66.8,67.05 67.9,67.05 69,67.05 70.1,67.05 71.2,67.05 72.3,67.05 63.5,68.15 64.6,68.15 65.7,68.15 66.8,68.15 67.9,68.15 69,68.15 70.1,68.15 71.2,68.15 72.3,68.15 66.8,69.25 67.9,69.25 69,69.25 70.1,69.25 71.2,69.25 72.3,69.25 63.5,70.25 64.6,70.25 65.7,70.25 66.8,70.35 67.9,70.35 69,70.35 70.1,70.35 71.2,70.35 72.3,70.35
OUT2: CN3.2 Q3.1 Q3.2 Q3.3 Q4.5 Q4.6 Q4.7 Q4.8 Q7.1 Q7.2 Q7.3 Q8.5 Q8.6 Q8.7 Q8.8 R29.1 R30.2 | length 4.4
  BOTTOM w0.3: R29.1@59.95,49.75 R30.2@61.3,49.75 62.9,49.75 ; 63.15,49.5 62.9,49.75 ; v1@63.15,50 62.9,49.75 ; v1@63.5,50.05 63.2,49.75 62.9,49.75
  other v1: 67.9,44.55 69,44.55 70.1,44.55 71.2,44.55 72.3,44.55 66.8,45.65 67.9,45.65 69,45.65 70.1,45.65 71.2,45.65 72.3,45.65 66.8,46.75 67.9,46.75 69,46.75 70.1,46.75 71.2,46.75 72.3,46.75 63.5,47.85 64.6,47.85 65.7,47.85 66.8,47.85 67.9,47.85 69,47.85 70.1,47.85 71.2,47.85 72.3,47.85 66.8,48.95 67.9,48.95 69,48.95 70.1,48.95 71.2,48.95 72.3,48.95 63.5,49.95 64.6,49.95 65.7,49.95 66.8,50.05 67.9,50.05 69,50.05 70.1,50.05 71.2,50.05 72.3,50.05
SH1: IC1.10 R23.2 | length 14.3
  TOP w0.3: IC1.10@49.775,62.05 51,62.05 v2(51.3,62.2)
  BOTTOM w0.3: v2(51.3,62.2) 50.95,62.2 50.7,62.45 50.7,64.2 56.55,70.05 R23.2@58.55,70.05
SH2: IC1.6 R29.2 | length 14.5
  TOP w0.3: IC1.6@49.15,59.925 49.15,59.45 49.4,59.2 v2(50,59.2)
  BOTTOM w0.3: v2(50,59.2) 50.35,59.05 56.6,52.8 56.6,51.7 R29.2@58.55,49.75
SIG595: CN4.4 IC2.13 R35.1 R37.2 | length 71.1
  BOTTOM w0.3: IC2.13@50.8,77.175 51.775,77.175 52.5,77.9 55.15,77.9 62.45,85.2 62.45,98.05 64.3,99.9 76.65,99.9 86.65,89.9 86.65,82.35 R37.2@87.5,81.5 R35.1@89.8,81.5 91.38,81.5 CN4.4@92.5,80.38
SIG638: IC2.3 Q13.B | length 3.9
  BOTTOM w0.4: Q13.B@41.65,74.8 43.175,74.8 44.05,73.925 IC2.3@45.2,73.925
SIG639: IC2.2 Q13.E R34.2 | length 7.5
  BOTTOM w0.4: 38.3,72.775 38.3,72.5 43.275,72.5 44.05,73.275 IC2.2@45.2,73.275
